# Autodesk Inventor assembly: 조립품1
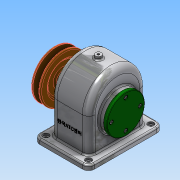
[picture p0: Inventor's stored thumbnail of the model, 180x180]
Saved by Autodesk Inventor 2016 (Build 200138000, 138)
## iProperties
Created: 2018-08
Part Number: 조립품1
Material: 일반
Document SubType Name: Assembly
Designer: Administrator
Author: Administrator
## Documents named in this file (14)
- C:\Users\Administrator\Desktop\480811V1012\답안조립품.iam
- C:\Users\Administrator\Desktop\480811V1012\본체.ipt
- C:\Users\Administrator\Desktop\480811V1012\축.ipt
- C:\Users\Administrator\Desktop\480811V1012\키 6x6x22.ipt
- C:\Users\Administrator\Desktop\480811V1012\스퍼기어.ipt
- C:\Users\Administrator\Desktop\480811V1012\베어링 6203.ipt
- C:\Users\Administrator\Desktop\480811V1012\뒤커버.ipt
- C:\Users\Administrator\Desktop\480811V1012\앞커버.ipt
- C:\Users\Administrator\Desktop\480811V1012\볼트 M4.ipt
- C:\Users\Administrator\Desktop\480811V1012\부시.ipt
- C:\Users\Administrator\Desktop\480811V1012\오일 실 28 40 8.ipt
- C:\Users\Administrator\Desktop\480811V1012\키 5x5x18.ipt
- C:\Users\Administrator\Desktop\480811V1012\V-벨트풀리.ipt
- C:\Users\Administrator\Desktop\480811V1012\멈춤나사 M4.ipt
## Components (1 placed, 1 different names)
1. V-벨트풀리:1
